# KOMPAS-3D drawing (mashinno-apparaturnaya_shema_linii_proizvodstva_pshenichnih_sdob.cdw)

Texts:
  ОУП-02068108-260601-96-2010
  Машинно-аппаратурная  схема линии производства  пшеничных сдобных сухарей
  Игорь
  Сухарные плиты
  Сухари
  Тесто
  Машинно-аппаратурная
  схема линии производства
  пшеничных сдобных сухарей
  Саранов И.А.
  Рязанов А.Н.
  УП-02068108-260601-2010-
Dimensions and other numbers on the sheet: 1; 2; 3; 4; 5; 6; 7; 8; 9; 10; 11; 14; 15; 12; 13; 0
